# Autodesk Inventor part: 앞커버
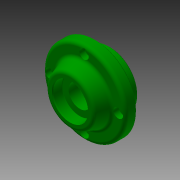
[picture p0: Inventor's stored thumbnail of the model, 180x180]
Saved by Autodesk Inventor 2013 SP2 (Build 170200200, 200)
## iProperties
Created: 2017-08
Part Number: 앞커버
Material: 알루미늄 6061
Document SubType Name: Modeling
Designer: mduedu
Density: 2.71 g/cm^3
Author: mduedu
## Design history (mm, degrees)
sketch "스케치1"
  geometry: C1 r 35 at (0, 0); 1 further point
  constraints: 1 centre point, 1 coincident
  dimensions: "d0" = 70 diameter of C1
extrude "돌출1" new body sketch "스케치1" distance "d1" = 10; taper "d2" = 0 deg
sketch "스케치2"
  geometry: C1 r 24 at (0, 0); 1 further point
  constraints: 1 centre point, 1 coincident
  dimensions: "d3" = 48 diameter of C1
node "작업 평면1"
sketch "스케치3"
  geometry: C1 r 20 at (0, 0); 1 further point
  constraints: 1 centre point, 1 coincident
  dimensions: "d5" = 40 diameter of C1
feature "로프트1" sketch "스케치3" dims "d6" = 0, "d7" = 90 deg, "d8" = 0, "d9" = 90 deg
sketch "스케치4"
  geometry: C1 r 24 at (0, 0) reference; 1 further point
extrude "돌출2" join sketch "스케치4" distance "d10" = 12; taper "d11" = 0 deg
hole "구멍1" diameter "d14" = 40; stored, may be unused: countersink angle "d18" = 90 deg, drill point angle "d20" = 0 deg; dims "d12" = 10, "d13" = 10, "d15" = 6, "d16" = 4, "d17" = 2, "d19" = 12
hole "구멍2" diameter "d23" = 36; stored, may be unused: countersink angle "d27" = 90 deg, drill point angle "d29" = 0 deg; dims "d24" = 6, "d25" = 4, "d26" = 2, "d28" = 5, "d88" = 10, "d89" = 10
hole "구멍3" diameter "d32" = 19; stored, may be unused: countersink angle "d36" = 90 deg, drill point angle "d38" = 0 deg; dims "d30" = 10, "d31" = 10, "d33" = 6, "d34" = 4, "d35" = 2, "d37" = 3
chamfer "모따기1" distance "d39" = 1; stored, may be unused: second distance "d40" = 2, angle "d41" = 45 deg
sketch "스케치5"
  geometry: C1 r 15 at (0, 0); 1 further point
  constraints: 1 centre point, 1 coincident
  dimensions: "d42" = 30 diameter of C1
extrude "돌출3" cut sketch "스케치5" distance "d43" = 8.3; taper "d44" = 0 deg
chamfer "모따기2" distance "d47" = 0.8; stored, may be unused: second distance "d48" = 2, angle "d49" = 30 deg
fillet "모깎기1" dims "d50" = 0.3
fillet "모깎기2" dims "d51" = 0.3
fillet "모깎기3" dims "d52" = 3
sketch "스케치6" dims "d53" = 66
  geometry: C1 r 24 at (0, 0) reference; C2 r 35 at (0, 0) reference; 6 further points
  constraints: 2 vertical alignment, 1 coincident, 7 other
  dimensions: "d56" = 360 deg dimension on point (0, 0) point (0, 33) (derived)
sketch "스케치9"
  geometry: 4 further points
  constraints: 4 other
hole "구멍6" sketch "스케치9" at (-29, 0), (0, -29), (29, 0), (0, 29) diameter "d72" = 4.5; stored, may be unused: countersink angle "d76" = 90 deg, drill point angle "d78" = 0 deg; dims "d73" = 6, "d74" = 8, "d75" = 4.6, "d77" = 8
fillet "모깎기4" dims "d79" = 3
fillet "모깎기5" dims "d80" = 3
fillet "모깎기6" dims "d81" = 3
chamfer "모따기3" distance "d82" = 1; stored, may be unused: second distance "d83" = 2, angle "d84" = 30 deg
node "솔리드1"
other parameters: "d4" = 12
